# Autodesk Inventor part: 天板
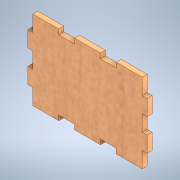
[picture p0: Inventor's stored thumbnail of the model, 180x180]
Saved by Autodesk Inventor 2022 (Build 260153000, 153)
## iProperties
Created: 2024-11
Part Number: 天板
Material: MDF 中密度繊維ボード
Document SubType Name: Modeling
Designer: shimizu
Density: 0.8 g/cm^3
Appearance: サクラ材 - ナチュラル 抑えた光沢
Author: shimizu
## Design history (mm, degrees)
sketch "スケッチ1"
  geometry: L1 (-25.119, 2.566)-(-27.619, 2.566); L2 (-27.619, 2.566)-(-27.619, -5.434); L3 (-27.619, -5.434)-(-25.119, -5.434); L4 (-25.119, -13.434)-(-27.619, -13.434); L5 (-27.619, -13.434)-(-27.619, -21.434); L6 (-27.619, -21.434)-(-25.119, -21.434); L7 (29.881, 2.566)-(32.381, 2.566); L8 (32.381, 2.566)-(32.381, -5.434); L9 (32.381, -5.434)-(29.881, -5.434); L10 (29.881, -13.434)-(32.381, -13.434); L11 (32.381, -13.434)-(32.381, -21.434); L12 (32.381, -21.434)-(29.881, -21.434); L13 (-25.119, 2.566)-(-25.119, 10.566); L14 (-25.119, -29.434)-(-25.119, -21.434); L15 (-25.119, -13.434)-(-25.119, -5.434); L16 (29.881, 10.566)-(29.881, 2.566); L17 (29.881, -5.434)-(29.881, -13.434); L18 (29.881, -21.434)-(29.881, -29.434); L19 (-4.119, -29.434)-(-4.119, -26.934); L20 (-4.119, -26.934)-(-12.119, -26.934); L21 (-12.119, -26.934)-(-12.119, -29.434); L22 (16.881, -29.434)-(16.881, -26.934); L23 (16.881, -26.934)-(8.881, -26.934); L24 (8.881, -26.934)-(8.881, -29.434); L25 (-4.119, 10.566)-(-4.119, 8.066); L26 (-4.119, 8.066)-(-12.119, 8.066); L27 (-12.119, 8.066)-(-12.119, 10.566); L28 (16.881, 10.566)-(16.881, 8.066); L29 (16.881, 8.066)-(8.881, 8.066); L30 (8.881, 8.066)-(8.881, 10.566); L31 (-25.119, 10.566)-(-12.119, 10.566); L32 (-4.119, 10.566)-(8.881, 10.566); L33 (16.881, 10.566)-(29.881, 10.566); L34 (-12.119, -29.434)-(-25.119, -29.434); L35 (29.881, -29.434)-(16.881, -29.434); L36 (8.881, -29.434)-(-4.119, -29.434); 1 further point
  constraints: 72 end point, 26 parallel, 13 perpendicular, 7 horizontal, 2 collinear
  dimensions: "d29" = 55 distance between parallel lines of L17 L15; "d30" = 35 distance between parallel lines of L20 L26; "d31" = 60 distance between parallel lines of L11 L5; "d32" = 13 distance of L21.end L14.start; "d33" = 13 distance of L24.end L19.start; "d34" = 13 distance of L18.end L22.start; "d35" = 13 distance of L13.end L27.end; "d36" = 13 distance of L25.start L30.end; "d37" = 13 distance of L28.start L16.start; "d38" = 8 distance of L28.end L29.end; "d39" = 8 distance of L25.end L26.end; "d40" = 8 distance of L22.end L23.end; "d41" = 8 distance of L19.end L20.end; "d42" = 8 distance of L9.end L10.start
extrude "押し出し1" new body sketch "スケッチ1" distance "d2" = 2.5; taper "d3" = 0 deg
node "ソリッド1"
